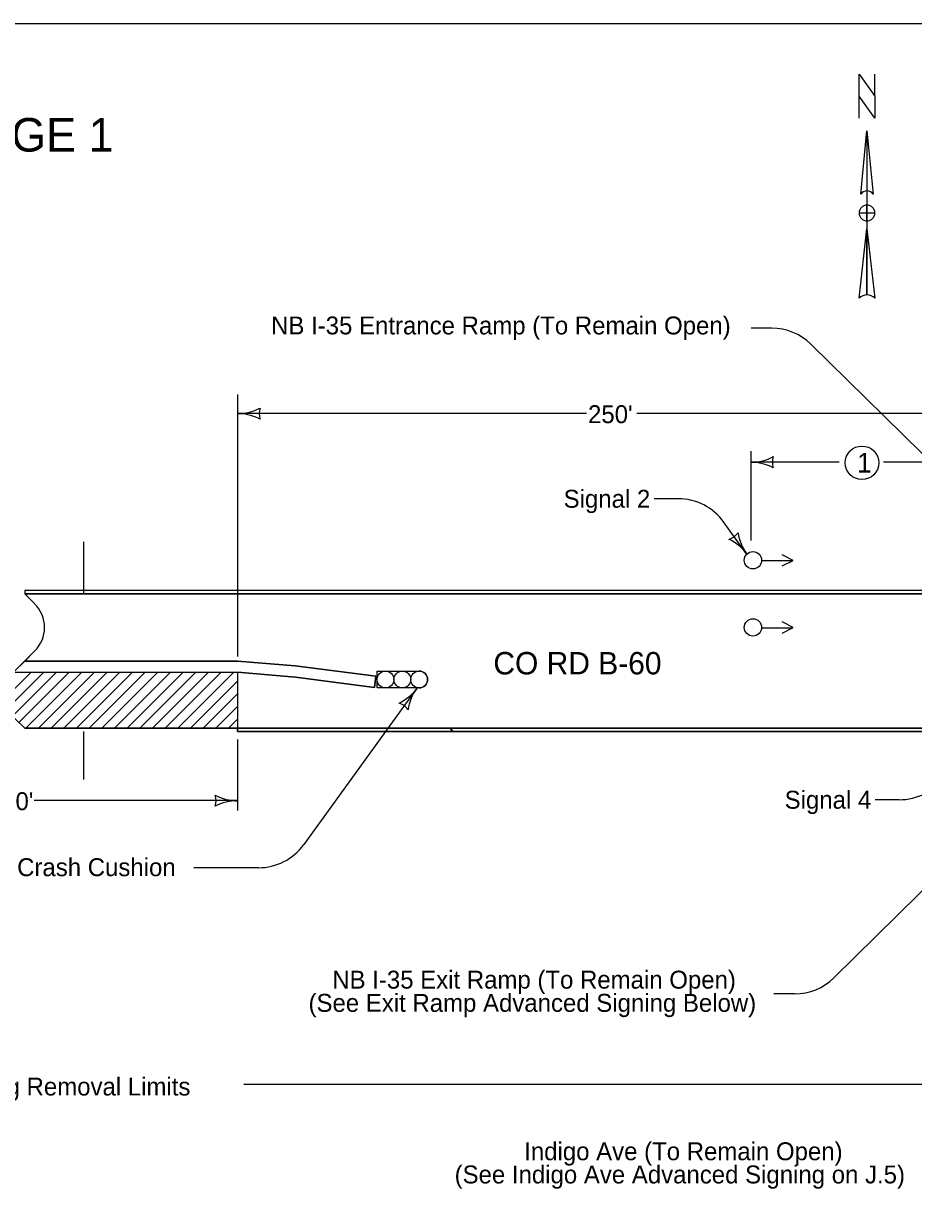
# Model space of a CAD drawing. Extents: x -2134934 to -2122394, y -2139046 to -2137036.
# Drawn here: x -2128661 to -2127867, y -2138081 to -2137036 of the extents above; entities that cross this region are included whole.
import ezdxf

# ---------------------------------------------------------------- set-up
doc = ezdxf.new("R2010")
doc.units = 0
for name, color, linetype in [('Barrier', 7, 'Continuous'), ('BridgeSuperStructureExisting', 7, 'Continuous'), ('Default', 7, 'Continuous'), ('dsnCellsNorthArrow', 7, 'Continuous'), ('dsnCellsScaleBlock', 7, 'Continuous'), ('DsnShtPlotIdentification', 7, 'Continuous'), ('DsnShtPlotShape', 7, 'Continuous')]:
    doc.layers.add(name, color=color, linetype=linetype)

msp = doc.modelspace()

# ---------------------------------------------------------------- linework, layer by layer
at = {"layer": 'BridgeSuperStructureExisting'}
for p, q in [((-2127993.4, -2137308), (-2128011.8, -2137308)), ((-2127958.3, -2137322.4), (-2127770.1, -2137507.7)), ((-2128470.1, -2137367.2), (-2128470.1, -2137601.1)), ((-2128158.6, -2137384.3), (-2128470.1, -2137384.3)), ((-2127812, -2137384.3), (-2128113.7, -2137384.3)), ((-2128011.9, -2137417.7), (-2128011.9, -2137497.7)), ((-2127933.2, -2137427.7), (-2128011.9, -2137427.7)), ((-2127811.9, -2137427.7), (-2127893.7, -2137427.7)), ((-2128076.8, -2137460.3), (-2128098.2, -2137460.3)), ((-2128016, -2137509.2), (-2128036.3, -2137481)), ((-2128607.6, -2137498.8), (-2128607.6, -2137545.2)), ((-2128002.4, -2137515.5), (-2127974.4, -2137515.5)), ((-2128660.1, -2137545.2), (-2128651.3, -2137553.9)), ((-2127160.1, -2137545.2), (-2128660.1, -2137545.2)), ((-2128660.1, -2137545.2), (-2128651.3, -2137553.9)), ((-2128002.4, -2137575.5), (-2127974.4, -2137575.5)), ((-2128651.3, -2137596.4), (-2128668.9, -2137613.9)), ((-2128660.1, -2137605.2), (-2128668.9, -2137613.9)), ((-2128651.3, -2137596.4), (-2128660.1, -2137605.2)), ((-2128470.1, -2137605.2), (-2128660.1, -2137605.2)), ((-2128470.1, -2137605.2), (-2128660.1, -2137605.2)), ((-2128660.1, -2137605.2), (-2128470.1, -2137605.2)), ((-2128660.1, -2137605.2), (-2128470.1, -2137605.2)), ((-2128418.6, -2137609.5), (-2128470.1, -2137605.2)), ((-2128470.1, -2137605.2), (-2128418.6, -2137609.5)), ((-2128470.1, -2137605.2), (-2128418.6, -2137609.5)), ((-2128654.4, -2137615.2), (-2128677.5, -2137638.3)), ((-2128643.1, -2137615.2), (-2128675.1, -2137647.2)), ((-2128631.8, -2137615.2), (-2128670.8, -2137654.2)), ((-2128670.1, -2137615.2), (-2128470.5, -2137615.2)), ((-2128670.1, -2137615.2), (-2128470.1, -2137615.2)), ((-2128620.4, -2137615.2), (-2128665.3, -2137660)), ((-2128609.1, -2137615.2), (-2128659.1, -2137665.2)), ((-2128597.8, -2137615.2), (-2128647.8, -2137665.2)), ((-2128586.5, -2137615.2), (-2128636.5, -2137665.2)), ((-2128575.2, -2137615.2), (-2128625.2, -2137665.2)), ((-2128563.9, -2137615.2), (-2128613.9, -2137665.2)), ((-2128552.6, -2137615.2), (-2128602.6, -2137665.2)), ((-2128591.2, -2137665.2), (-2128541.2, -2137615.2)), ((-2128529.9, -2137615.2), (-2128579.9, -2137665.2)), ((-2128518.6, -2137615.2), (-2128568.6, -2137665.2)), ((-2128507.3, -2137615.2), (-2128557.3, -2137665.2)), ((-2128496, -2137615.2), (-2128546, -2137665.2)), ((-2128484.7, -2137615.2), (-2128534.7, -2137665.2)), ((-2128473.4, -2137615.2), (-2128523.4, -2137665.2)), ((-2128470.5, -2137615.2), (-2128470.4, -2137615.2)), ((-2128470.4, -2137615.2), (-2128470.1, -2137615.2)), ((-2128470.1, -2137615.2), (-2128470.1, -2137665.2)), ((-2128470.1, -2137615.2), (-2128470.1, -2137615.2)), ((-2128470.1, -2137615.2), (-2128418.4, -2137619.5)), ((-2128470.1, -2137615.2), (-2128418.4, -2137619.5)), ((-2128418.4, -2137619.5), (-2128470.1, -2137615.2)), ((-2128470.1, -2137615.2), (-2128470.1, -2137665.2)), ((-2128346.6, -2137618.8), (-2128418.6, -2137609.5)), ((-2128346.6, -2137618.8), (-2128418.6, -2137609.5)), ((-2128418.6, -2137609.5), (-2128346.6, -2137618.8)), ((-2128418.6, -2137609.5), (-2128346.6, -2137618.8)), ((-2128345.6, -2137629.1), (-2128345.6, -2137614.1)), ((-2128345.6, -2137614.1), (-2128308.1, -2137614.1)), ((-2128345.6, -2137629.1), (-2128345.6, -2137614.1)), ((-2128345.6, -2137614.1), (-2128308.1, -2137614.1)), ((-2128470.1, -2137623.2), (-2128512.1, -2137665.2)), ((-2128418.4, -2137619.5), (-2128347.9, -2137628.7)), ((-2128418.4, -2137619.5), (-2128347.9, -2137628.7)), ((-2128347.9, -2137628.7), (-2128418.4, -2137619.5)), ((-2128347.9, -2137628.7), (-2128346.6, -2137618.8)), ((-2128346.6, -2137618.8), (-2128347.9, -2137628.7)), ((-2128346.6, -2137618.8), (-2128347.9, -2137628.7)), ((-2128470.1, -2137634.5), (-2128500.8, -2137665.2)), ((-2128310.2, -2137629.5), (-2128411, -2137769)), ((-2128308.1, -2137629.1), (-2128345.6, -2137629.1)), ((-2128308.1, -2137629.1), (-2128345.6, -2137629.1)), ((-2128470.1, -2137645.8), (-2128489.5, -2137665.2)), ((-2128668.9, -2137656.4), (-2128660.1, -2137665.2)), ((-2128470.1, -2137657.1), (-2128478.2, -2137665.2)), ((-2128607.6, -2137668.2), (-2128607.6, -2137710.9)), ((-2128470.1, -2137665.2), (-2127160.1, -2137665.2)), ((-2128470.1, -2137675.2), (-2128470.1, -2137738.5)), ((-2127937.8, -2137887.9), (-2127749.7, -2137702.6)), ((-2128470.1, -2137729.8), (-2128651.7, -2137729.8)), ((-2127879.5, -2137729), (-2127900.9, -2137729)), ((-2128451.5, -2137789.7), (-2128509.3, -2137789.7)), ((-2127972.9, -2137902.3), (-2127991.4, -2137902.3)), ((-2127805.1, -2137983.3), (-2128464.5, -2137983.3))]:
    msp.add_line(p, q, dxfattribs=at)
for points in [[(-2127984.1, -2137520.3), (-2127974.1, -2137515.3), (-2127984.1, -2137510.3)], [(-2127984.1, -2137580.3), (-2127974.1, -2137575.3), (-2127984.1, -2137570.3)], [(-2128660.1, -2137605.2), (-2128660.1, -2137605.2)], [(-2128660.1, -2137605.2), (-2128660.1, -2137605.2)], [(-2128470.5, -2137615.2), (-2128470.5, -2137615.2)], [(-2128308.1, -2137614.1), (-2128308.1, -2137614.1)], [(-2128308.1, -2137629.1), (-2128308.1, -2137629.1)], [(-2128470.1, -2137665.2), (-2128660.1, -2137665.2)]]:
    msp.add_lwpolyline(points, dxfattribs=at)
for centre, radius in [((-2127912.8, -2137428.2), 15), ((-2128010.1, -2137515.2), 7.74), ((-2128010.1, -2137575.2), 7.74), ((-2128338.1, -2137621.6), 7.5), ((-2128338.1, -2137621.6), 7.5), ((-2128323.1, -2137621.6), 7.5), ((-2128323.1, -2137621.6), 7.5), ((-2128308.1, -2137621.6), 7.5), ((-2128308.1, -2137621.6), 7.5)]:
    msp.add_circle(centre, radius, dxfattribs=at)
for centre, radius, start, end in [((-2127993.4, -2137358), 50, 45.4365, 90), ((-2128011.9, -2137385.2), 42.5, 270, 298.0725), ((-2128011.9, -2137470.2), 42.5, 61.9275, 90), ((-2127976.3, -2137427.7), 16.4, 162.2666, 197.7334), ((-2128076.8, -2137510.3), 50, 35.862, 90), ((-2128672.5, -2137575.2), 30, 315, 45), ((-2128672.5, -2137575.2), 30, 315, 45), ((-2128308.1, -2137621.6), 7.5, 270.0028, 89.9972), ((-2127879.5, -2137679), 50, 270, 324.138), ((-2128505.8, -2137729.8), 16.4, 342.2666, 17.7334), ((-2128470.1, -2137687.4), 42.5, 241.9275, 270), ((-2128470.1, -2137772.3), 42.5, 90, 118.0725), ((-2128451.5, -2137739.7), 50, 270, 324.138), ((-2127972.9, -2137852.3), 50, 270, 314.5635)]:
    msp.add_arc(centre, radius, start, end, dxfattribs=at)
at = {"layer": 'Default'}
msp.add_lwpolyline([(-2130232, -2137035.9), (-2127097, -2137035.9), (-2127097, -2139045.9), (-2130232, -2139045.9)], close=True, dxfattribs=at)
at = {"layer": 'dsnCellsScaleBlock'}
for p, q in [((-2127908.3, -2137131.9), (-2127902.7, -2137188.3)), ((-2127908.3, -2137131.9), (-2127908.3, -2137278.4)), ((-2127913.7, -2137187.7), (-2127912.7, -2137186.6)), ((-2127913.9, -2137188.3), (-2127913.9, -2137188.3)), ((-2127915.3, -2137281.2), (-2127908.3, -2137219.2)), ((-2127908.3, -2137212.2), (-2127908.3, -2137212.2))]:
    msp.add_line(p, q, dxfattribs=at)
msp.add_lwpolyline([(-2127901.3, -2137120.6), (-2127915.3, -2137100.9), (-2127915.3, -2137081.2), (-2127901.3, -2137100.9)], close=True, dxfattribs=at)
for points in [[(-2127915.3, -2137120.6), (-2127915.3, -2137081.2), (-2127901.3, -2137100.9), (-2127901.3, -2137081.2)], [(-2127913.9, -2137188.3), (-2127908.3, -2137131.9), (-2127908.3, -2137185.4)], [(-2127901.3, -2137205.2), (-2127908.3, -2137205.2), (-2127908.3, -2137198.1)], [(-2127908.3, -2137212.2), (-2127908.3, -2137205.2), (-2127915.3, -2137205.2)], [(-2127908.3, -2137278.4), (-2127908.3, -2137219.2), (-2127901.3, -2137281.2)]]:
    msp.add_lwpolyline(points, dxfattribs=at)
for centre, radius, start, end in [((-2127908.3, -2137192.5), 7.04, 90.0204, 143.1257), ((-2127908.3, -2137192.5), 7.04, 36.8481, 90.0218), ((-2127908.3, -2137205.2), 7.04, 90, 180), ((-2127908.3, -2137205.2), 7.04, 360, 90), ((-2127908.3, -2137205.2), 7.04, 180, 270), ((-2127908.3, -2137205.2), 7.04, 270, 360), ((-2127908.3, -2137288.6), 10.2, 89.9894, 133.619), ((-2127908.3, -2137288.6), 10.2, 46.4021, 90.0006)]:
    msp.add_arc(centre, radius, start, end, dxfattribs=at)
at = {"layer": 'DsnShtPlotIdentification'}
for p, q in [((-2127160.1, -2137542.2), (-2128660.1, -2137542.2)), ((-2127160.1, -2137542.2), (-2128660.1, -2137542.2)), ((-2128660.1, -2137542.2), (-2128660.1, -2137545.2)), ((-2127160.1, -2137545.2), (-2128660.1, -2137545.2)), ((-2128660.1, -2137545.2), (-2127810.1, -2137545.2)), ((-2128660.1, -2137665.2), (-2127159.5, -2137665.2)), ((-2128470.1, -2137665.2), (-2128470.1, -2137668.2)), ((-2128470.1, -2137668.2), (-2128470.1, -2137665.2)), ((-2128470.1, -2137668.2), (-2128278.1, -2137668.2)), ((-2128278.1, -2137668.2), (-2128280.3, -2137665.2)), ((-2128280.3, -2137665.2), (-2128278.1, -2137668.2)), ((-2127805.1, -2137665.2), (-2128280.3, -2137665.2)), ((-2128278.1, -2137668.2), (-2127805.1, -2137668.2))]:
    msp.add_line(p, q, dxfattribs=at)
for points in [[(-2128471.3, -2137545.2), (-2127158.8, -2137545.2)], [(-2127160.1, -2137665.2), (-2128470.1, -2137665.2)], [(-2128280.3, -2137665.2), (-2128469.7, -2137665.2), (-2128470.1, -2137665.2)], [(-2127160.1, -2137668.2), (-2128470.1, -2137668.2)]]:
    msp.add_lwpolyline(points, dxfattribs=at)
at = {"layer": 'DsnShtPlotShape'}
for centre, radius, start, end in [((-2128470.1, -2137341.8), 42.5, 270, 298.0725), ((-2128470.1, -2137426.8), 42.5, 61.9275, 90), ((-2128434.5, -2137384.3), 16.4, 162.2666, 197.7334), ((-2128036.7, -2137481), 16.4, 288.5657, 324.0324), ((-2127981.3, -2137484.5), 42.5, 188.2265, 216.299), ((-2128049.8, -2137534.8), 42.5, 36.299, 64.3715), ((-2128344.4, -2137604.4), 42.5, 295.6285, 323.701), ((-2128275.9, -2137654.7), 42.5, 143.701, 171.7735), ((-2128331.3, -2137658.2), 16.4, 35.9676, 71.4343)]:
    msp.add_arc(centre, radius, start, end, dxfattribs=at)

# ---------------------------------------------------------------- texts
at = {"layer": 'Barrier'}
msp.add_text('STAGE 1', height=30, dxfattribs=at).set_placement((-2128750.3, -2137150.4))
at = {"layer": 'BridgeSuperStructureExisting'}
for s, height, p in [('NB I-35 Entrance Ramp (To Remain Open)', 16, (-2128440.2, -2137313.6)), ("250'", 16, (-2128157.3, -2137392.8)), ('1', 17.5, (-2127917.2, -2137436.9)), ('Signal 2', 16, (-2128179.1, -2137468.3)), ('Signal 4', 16, (-2127981.8, -2137737)), ("460'", 16, (-2128692.2, -2137738.3)), ('Temporary Crash Cushion', 16, (-2128776.3, -2137797.2)), ('NB I-35 Exit Ramp (To Remain Open)', 16, (-2128385.6, -2137897.6)), ('(See Exit Ramp Advanced Signing Below)', 16, (-2128406.8, -2137918.3)), ('Pavement Marking Removal Limits', 16, (-2128842.8, -2137993)), ('Indigo Ave (To Remain Open)', 16, (-2128214.3, -2138050.8)), ('(See Indigo Ave Advanced Signing on J.5)', 16, (-2128276.4, -2138071.5))]:
    msp.add_text(s, height=height, dxfattribs=at).set_placement(p)
at = {"layer": 'dsnCellsNorthArrow'}
msp.add_text('CO RD B-60', height=20, dxfattribs=at).set_placement((-2128241.8, -2137617.1))

doc.saveas('drawing.dxf')
